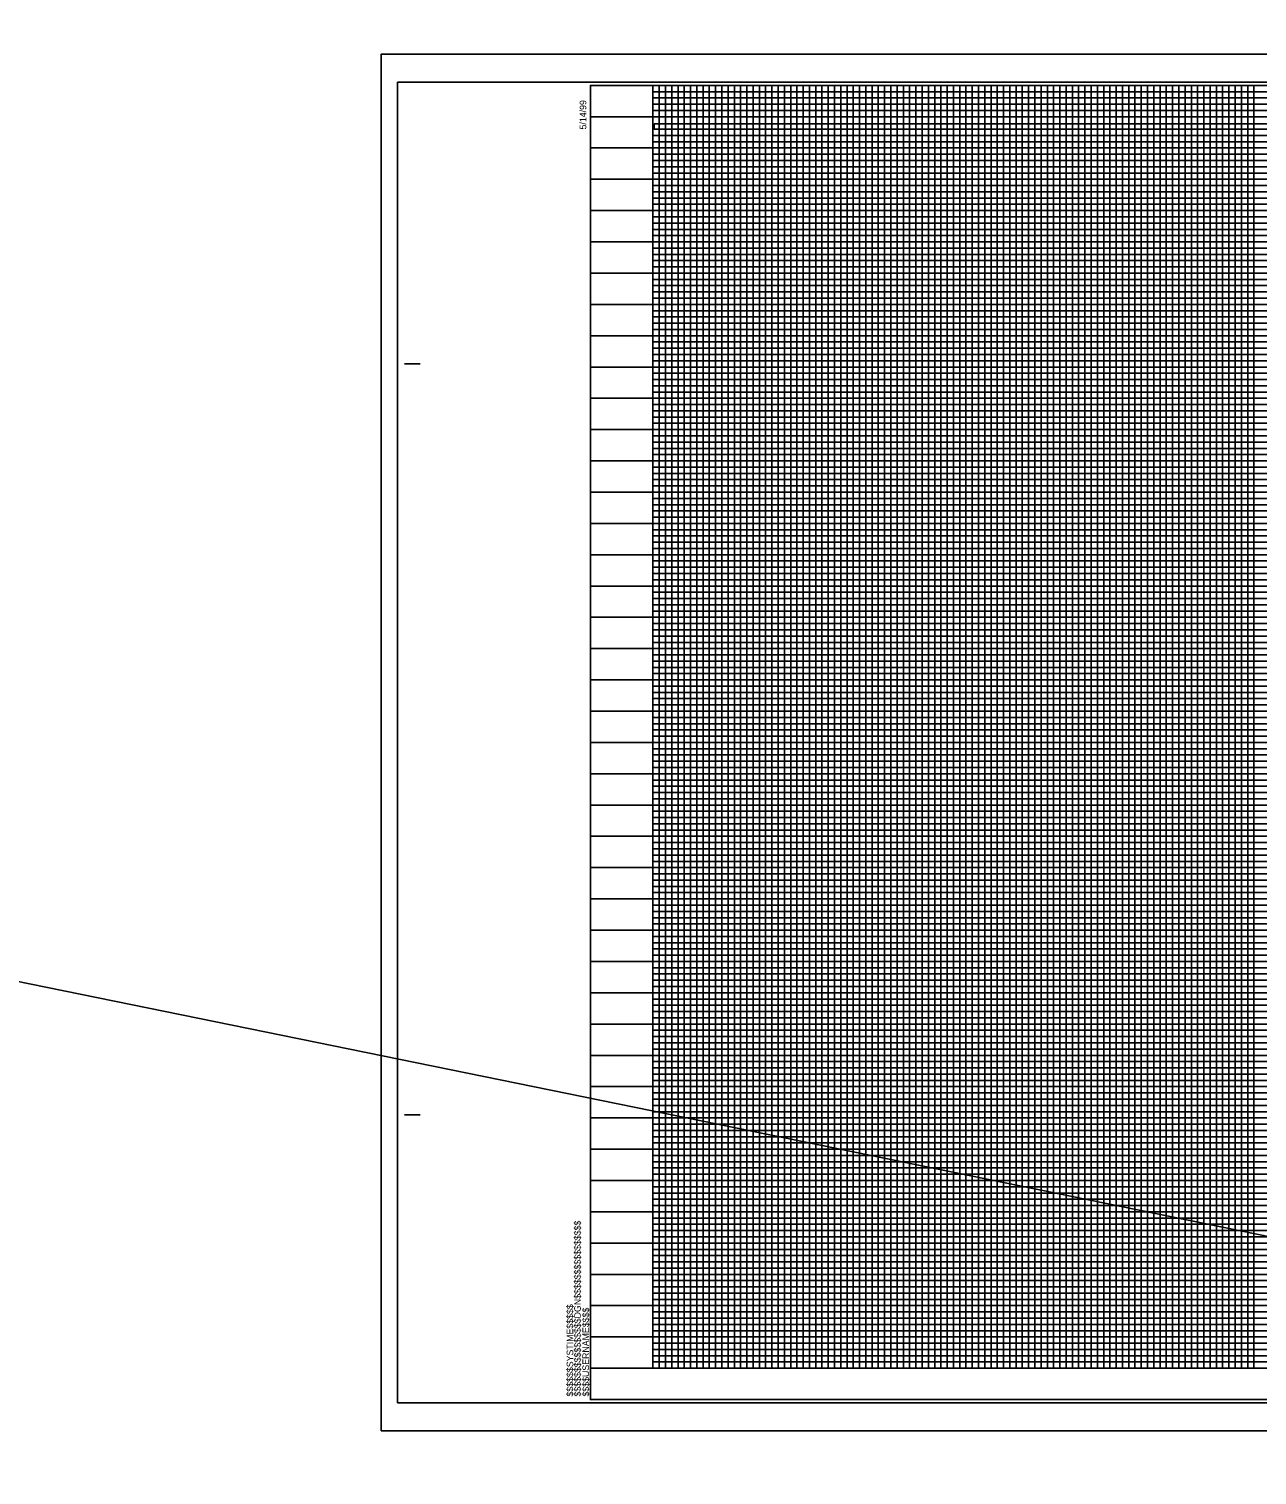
# Model space of a CAD drawing. Extents: x 2345490 to 2445302, y 465165 to 573888.
# Drawn here: x 2381268 to 2382249, y 553101 to 554257 of the extents above; entities that cross this region are included whole.
import ezdxf

# ---------------------------------------------------------------- set-up
doc = ezdxf.new("R2010")
doc.units = 0
for name, color, linetype in [('Old_Level_18', 7, 'Continuous'), ('Old_Level_40', 7, 'Continuous'), ('Old_Level_41', 7, 'Continuous'), ('Old_Level_42', 7, 'Continuous'), ('Old_Level_43', 7, 'Continuous'), ('Old_Level_50', 7, 'Continuous'), ('Old_Level_51', 7, 'Continuous'), ('Old_Level_52', 7, 'Continuous'), ('Old_Level_62', 7, 'Continuous')]:
    doc.layers.add(name, color=color, linetype=linetype)

msp = doc.modelspace()

# ---------------------------------------------------------------- linework, layer by layer
at = {"layer": 'Old_Level_18'}
msp.add_line((2381716.79875, 553161.782), (2381716.79875, 553161.782), dxfattribs=at)
msp.add_line((2381716.79875, 553161.782), (2381716.79875, 553161.782), dxfattribs=at)
msp.add_lwpolyline([(2383216.79875, 554211.782), (2381716.79875, 554211.782), (2381716.79875, 553161.782), (2383216.79875, 553161.782)], close=True, dxfattribs=at)
at = {"layer": 'Old_Level_40'}
msp.add_line((2381716.79875, 553161.782), (2381716.79875, 553161.782), dxfattribs=at)
msp.add_line((2381716.79875, 553161.782), (2381716.79875, 553161.782), dxfattribs=at)
msp.add_line((2381716.79875, 553161.782), (2381716.79875, 553161.782), dxfattribs=at)
msp.add_line((2381716.79875, 553161.782), (2381716.79875, 553161.782), dxfattribs=at)
at = {"layer": 'Old_Level_41'}
for p, q in [((2381568.29875, 553989.282), (2381580.79875, 553989.282)), ((2381568.29875, 553389.282), (2381580.79875, 553389.282)), ((2383216.79875, 553186.782), (2381716.79875, 553186.782))]:
    msp.add_line(p, q, dxfattribs=at)
for points in [[(2381716.79875, 554211.782), (2381766.79875, 554211.782), (2381766.79875, 553186.782), (2381816.79875, 553186.782), (2381816.79875, 554211.782), (2381866.79875, 554211.782), (2381866.79875, 553186.782), (2381916.79875, 553186.782), (2381916.79875, 554211.782), (2381966.79875, 554211.782), (2381966.79875, 553186.782), (2382016.79875, 553186.782), (2382016.79875, 554211.782), (2382066.79875, 554211.782), (2382066.79875, 553186.782), (2382116.79875, 553186.782), (2382116.79875, 554211.782), (2382166.79875, 554211.782), (2382166.79875, 553186.782), (2382216.79875, 553186.782), (2382216.79875, 554211.782), (2382266.79875, 554211.782)], [(2381791.79875, 553186.782), (2381791.79875, 554211.782), (2381841.79875, 554211.782), (2381841.79875, 553186.782), (2381891.79875, 553186.782), (2381891.79875, 554211.782), (2381941.79875, 554211.782), (2381941.79875, 553186.782), (2381991.79875, 553186.782), (2381991.79875, 554211.782), (2382041.79875, 554211.782), (2382041.79875, 553186.782), (2382091.79875, 553186.782), (2382091.79875, 554211.782), (2382141.79875, 554211.782), (2382141.79875, 553186.782), (2382191.79875, 553186.782), (2382191.79875, 554211.782), (2382241.79875, 554211.782), (2382241.79875, 553186.782), (2382291.79875, 553186.782)], [(2381716.79875, 554161.782), (2383016.74875, 554161.782)], [(2383016.74875, 554111.782), (2381716.79875, 554111.782), (2381716.79875, 554061.732), (2383216.79875, 554061.732)], [(2383216.79875, 554036.782), (2381716.79875, 554036.782), (2381716.79875, 554086.782), (2383016.74875, 554086.782)], [(2383216.79875, 554011.782), (2381716.79875, 554011.782), (2381716.79875, 553961.782), (2383216.79875, 553961.782)], [(2383216.79875, 553936.782), (2381716.79875, 553936.782), (2381716.79875, 553986.782), (2383216.79875, 553986.782)], [(2383216.79875, 553911.782), (2381716.79875, 553911.782), (2381716.79875, 553861.782), (2383216.79875, 553861.782)], [(2383216.79875, 553811.782), (2381716.79875, 553811.782), (2381716.79875, 553761.782), (2383216.79875, 553761.782)], [(2383216.79875, 553711.782), (2381716.79875, 553711.782), (2381716.79875, 553661.782), (2383216.79875, 553661.782)], [(2383216.79875, 553611.782), (2381716.79875, 553611.782), (2381716.79875, 553561.782), (2383216.79875, 553561.782)], [(2383216.79875, 553536.782), (2381716.79875, 553536.782), (2381716.79875, 553586.782), (2383216.79875, 553586.782)], [(2383216.79875, 553511.782), (2381716.79875, 553511.782), (2381716.79875, 553461.782), (2383216.79875, 553461.782)], [(2383216.79875, 553436.782), (2381716.79875, 553436.782), (2381716.79875, 553486.782), (2383216.79875, 553486.782)], [(2383216.79875, 553411.782), (2381716.79875, 553411.782), (2381716.79875, 553361.782), (2383216.79875, 553361.782)], [(2383216.79875, 553311.782), (2381716.79875, 553311.782), (2381716.79875, 553261.782), (2383216.79875, 553261.782)], [(2383216.79875, 553236.782), (2381716.79875, 553236.782), (2381716.79875, 553286.782), (2383216.79875, 553286.782)], [(2383216.79875, 553211.782), (2381716.79875, 553211.782)], [(2381754.29875, 553161.782), (2381754.29875, 553161.782)]]:
    msp.add_lwpolyline(points, dxfattribs=at)
at = {"layer": 'Old_Level_42'}
for points in [[(2383016.74875, 554136.782), (2381716.89875, 554136.782), (2381716.89875, 554186.732), (2383016.74875, 554186.732)], [(2383216.79875, 553836.782), (2381716.79875, 553836.782), (2381716.79875, 553886.782), (2383216.79875, 553886.782)], [(2383216.79875, 553736.782), (2381716.79875, 553736.782), (2381716.79875, 553786.782), (2383216.79875, 553786.782)], [(2383216.79875, 553636.782), (2381716.79875, 553636.782), (2381716.79875, 553686.782), (2383216.79875, 553686.782)], [(2383216.79875, 553336.782), (2381716.79875, 553336.782), (2381716.79875, 553386.782), (2383216.79875, 553386.782)]]:
    msp.add_lwpolyline(points, dxfattribs=at)
at = {"layer": 'Old_Level_43'}
for p, q in [((2383166.79875, 554031.782), (2381766.79875, 554031.782)), ((2381766.79875, 554031.782), (2381766.79875, 554026.782)), ((2381766.79875, 554026.782), (2383166.79875, 554026.782)), ((2383166.79875, 554006.782), (2381766.79875, 554006.782))]:
    msp.add_line(p, q, dxfattribs=at)
for points in [[(2381771.79875, 554211.782), (2381776.79875, 554211.782), (2381781.79875, 554211.782), (2381786.79875, 554211.782), (2381796.79875, 554211.782), (2381763.74875, 554211.782), (2381768.74875, 554211.782), (2381726.79875, 554211.782), (2381731.79875, 554211.782), (2381736.79875, 554211.782), (2381746.79875, 554211.782), (2381751.79875, 554211.782), (2381756.79875, 554211.782), (2381761.79875, 554211.782), (2381771.79875, 554211.782), (2381771.79875, 553186.782), (2381776.79875, 553186.782), (2381776.79875, 554211.782), (2381781.79875, 554211.782), (2381781.79875, 553186.782), (2381786.79875, 553186.782), (2381786.79875, 554211.782), (2381796.79875, 554211.782), (2381796.79875, 553186.782), (2381801.79875, 553186.782), (2381801.79875, 554211.782), (2381806.79875, 554211.782), (2381806.79875, 553186.782), (2381811.79875, 553186.782), (2381811.79875, 554211.782), (2381821.79875, 554211.782), (2381821.79875, 553186.782), (2381826.79875, 553186.782), (2381826.79875, 554211.782), (2381831.79875, 554211.782), (2381831.79875, 553186.782), (2381836.79875, 553186.782), (2381836.79875, 554211.782), (2381846.79875, 554211.782), (2381846.79875, 553186.782), (2381851.79875, 553186.782), (2381851.79875, 554211.782), (2381856.79875, 554211.782), (2381856.79875, 553186.782), (2381861.79875, 553186.782), (2381861.79875, 554211.782), (2381871.79875, 554211.782), (2381871.79875, 553186.782), (2381876.79875, 553186.782), (2381876.79875, 554211.782), (2381881.79875, 554211.782), (2381881.79875, 553186.782), (2381886.79875, 553186.782), (2381886.79875, 554211.782), (2381896.79875, 554211.782), (2381896.79875, 553186.782), (2381901.79875, 553186.782), (2381901.79875, 554211.782), (2381906.79875, 554211.782), (2381906.79875, 553186.782), (2381911.79875, 553186.782), (2381911.79875, 554211.782), (2381921.79875, 554211.782), (2381921.79875, 553186.782), (2381926.79875, 553186.782), (2381926.79875, 554211.782), (2381931.79875, 554211.782), (2381931.79875, 553186.782)], [(2383016.74875, 554206.782), (2381766.79875, 554206.782), (2381766.79875, 554201.782), (2383016.74875, 554201.782)], [(2381931.79875, 553186.782), (2381936.79875, 553186.782), (2381936.79875, 554211.782), (2381946.79875, 554211.782), (2381946.79875, 553186.782), (2381951.79875, 553186.782), (2381951.79875, 554211.782), (2381956.79875, 554211.782), (2381956.79875, 553186.782), (2381961.79875, 553186.782), (2381961.79875, 554211.782), (2381971.79875, 554211.782), (2381971.79875, 553186.782), (2381976.79875, 553186.782), (2381976.79875, 554211.782), (2381976.79875, 554211.782), (2381981.79875, 554211.782), (2381981.79875, 553186.782), (2381986.79875, 553186.782), (2381986.79875, 554211.782), (2381996.79875, 554211.782), (2381996.79875, 553186.782), (2382001.79875, 553186.782), (2382001.79875, 554211.782), (2382006.79875, 554211.782), (2382006.79875, 553186.782), (2382011.79875, 553186.782), (2382011.79875, 554211.782), (2382021.79875, 554211.782), (2382021.79875, 553186.782), (2382026.79875, 553186.782), (2382026.79875, 554211.782), (2382031.79875, 554211.782), (2382031.79875, 553186.782), (2382036.79875, 553186.782), (2382036.79875, 554211.782), (2382046.79875, 554211.782), (2382046.79875, 553186.782), (2382051.79875, 553186.782), (2382051.79875, 554211.782), (2382056.79875, 554211.782), (2382056.79875, 553186.782), (2382061.79875, 553186.782), (2382061.79875, 554211.782), (2382071.79875, 554211.782), (2382071.79875, 553186.782), (2382076.79875, 553186.782), (2382076.79875, 554211.782), (2382081.79875, 554211.782), (2382081.79875, 553186.782), (2382086.79875, 553186.782), (2382086.79875, 554211.782), (2382096.79875, 554211.782), (2382096.79875, 553186.782), (2382111.79875, 553186.782), (2382111.79875, 554211.782), (2382121.79875, 554211.782), (2382121.79875, 553186.782), (2382126.79875, 553186.782), (2382126.79875, 554211.782), (2382131.79875, 554211.782), (2382131.79875, 553186.782), (2382136.79875, 553186.782), (2382136.79875, 554211.782), (2382146.79875, 554211.782), (2382146.79875, 553186.782), (2382151.79875, 553186.782), (2382151.79875, 554211.782), (2382156.79875, 554211.782), (2382156.79875, 553186.782), (2382161.79875, 553186.782), (2382161.79875, 554211.782), (2382171.79875, 554211.782), (2382171.79875, 553186.782), (2382176.79875, 553186.782), (2382176.79875, 554211.782), (2382181.79875, 554211.782), (2382181.79875, 553186.782), (2382186.79875, 553186.782), (2382186.79875, 554211.782), (2382196.79875, 554211.782), (2382196.79875, 553186.782), (2382201.79875, 553186.782), (2382201.79875, 554211.782), (2382206.79875, 554211.782), (2382206.79875, 553186.782), (2382211.79875, 553186.782), (2382211.79875, 554211.782), (2382221.79875, 554211.782), (2382221.79875, 553186.782), (2382226.79875, 553186.782), (2382226.79875, 554211.782), (2382231.79875, 554211.782), (2382231.79875, 553186.782), (2382236.79875, 553186.782), (2382236.79875, 554211.782), (2382246.79875, 554211.782), (2382246.79875, 553186.782)], [(2382101.79875, 554211.782), (2382101.79875, 553186.782), (2382106.79875, 553186.782), (2382106.79875, 554211.782)], [(2382101.79875, 554211.182), (2382101.79875, 553186.782), (2382106.79875, 553186.782), (2382106.79875, 554211.182)], [(2383016.74875, 554196.782), (2381766.79875, 554196.782), (2381766.79875, 554191.782), (2383016.74875, 554191.782)], [(2383016.74875, 554181.032), (2381767.79875, 554181.032), (2381767.79875, 554176.782), (2383016.74875, 554176.782)], [(2383016.74875, 554171.782), (2381766.79875, 554171.782), (2381766.79875, 554166.782), (2383016.74875, 554166.782)], [(2383016.74875, 554156.782), (2381766.79875, 554156.782), (2381766.79875, 554151.782), (2383016.74875, 554151.782)], [(2383016.74875, 554146.782), (2381766.79875, 554146.782), (2381766.79875, 554141.782), (2383016.74875, 554141.782)], [(2383016.74875, 554131.782), (2381766.79875, 554131.782), (2381766.79875, 554126.782), (2383016.74875, 554126.782)], [(2383016.74875, 554121.782), (2381766.79875, 554121.782), (2381766.79875, 554116.782), (2383016.74875, 554116.782)], [(2383016.74875, 554106.782), (2381766.79875, 554106.782), (2381766.79875, 554101.782), (2383016.74875, 554101.782)], [(2383016.74875, 554096.782), (2381766.79875, 554096.782), (2381766.79875, 554091.782), (2383016.74875, 554091.782)], [(2383016.74875, 554081.782), (2381766.79875, 554081.782), (2381766.79875, 554076.782), (2383016.74875, 554076.782)], [(2383166.79875, 554071.782), (2381766.79875, 554071.782), (2381766.79875, 554071.782), (2381766.79875, 554051.782), (2383166.79875, 554051.782)], [(2381766.79875, 554066.782), (2383166.79875, 554066.782)], [(2383166.79875, 554056.782), (2381766.79875, 554056.782)], [(2383166.79875, 554046.782), (2381766.79875, 554046.782), (2381766.79875, 554041.782), (2383166.79875, 554041.782)], [(2383166.79875, 554021.782), (2381766.79875, 554021.782), (2381766.79875, 554016.782), (2383166.79875, 554016.782)], [(2383166.79875, 554001.782), (2381766.79875, 554001.782), (2381766.79875, 553996.782), (2383166.79875, 553996.782)], [(2383166.79875, 553991.782), (2381766.79875, 553991.782)], [(2381766.79875, 553981.782), (2383166.79875, 553981.782)], [(2383166.79875, 553976.782), (2381766.79875, 553976.782), (2381766.79875, 553971.782), (2383166.79875, 553971.782)], [(2383166.79875, 553966.782), (2381766.79875, 553966.782), (2381766.79875, 553956.782), (2383166.79875, 553956.782)], [(2383166.79875, 553951.782), (2381766.79875, 553951.782), (2381766.79875, 553946.782), (2383166.79875, 553946.782)], [(2383166.79875, 553941.782), (2381766.79875, 553941.782), (2381766.79875, 553931.782), (2383166.79875, 553931.782)], [(2383166.79875, 553926.782), (2381766.79875, 553926.782), (2381766.79875, 553921.782), (2383166.79875, 553921.782)], [(2383166.79875, 553916.782), (2381766.79875, 553916.782), (2381766.79875, 553906.782), (2383166.79875, 553906.782)], [(2383166.79875, 553901.782), (2381766.79875, 553901.782), (2381766.79875, 553896.782), (2383166.79875, 553896.782)], [(2383166.79875, 553891.782), (2381766.79875, 553891.782), (2381766.79875, 553881.782), (2383166.79875, 553881.782)], [(2383166.79875, 553876.782), (2381766.79875, 553876.782), (2381766.79875, 553871.782), (2383166.79875, 553871.782)], [(2383166.79875, 553866.782), (2381766.79875, 553866.782), (2381766.79875, 553856.782), (2383166.79875, 553856.782)], [(2383166.79875, 553851.782), (2381766.79875, 553851.782), (2381766.79875, 553846.782), (2383166.79875, 553846.782)], [(2383166.79875, 553841.782), (2381766.79875, 553841.782), (2381766.79875, 553831.782), (2383166.79875, 553831.782)], [(2383166.79875, 553826.782), (2381766.79875, 553826.782), (2381766.79875, 553821.782), (2383166.79875, 553821.782)], [(2383166.79875, 553816.782), (2381766.79875, 553816.782), (2381766.79875, 553806.782), (2383166.79875, 553806.782)], [(2383166.79875, 553801.782), (2381766.79875, 553801.782), (2381766.79875, 553796.782), (2383166.79875, 553796.782)], [(2383166.79875, 553791.782), (2381766.79875, 553791.782), (2381766.79875, 553781.782), (2383166.79875, 553781.782)], [(2383166.79875, 553776.782), (2381766.79875, 553776.782), (2381766.79875, 553771.782), (2383166.79875, 553771.782)], [(2383166.79875, 553766.782), (2381766.79875, 553766.782), (2381766.79875, 553756.782), (2383166.79875, 553756.782)], [(2383166.79875, 553751.782), (2381766.79875, 553751.782), (2381766.79875, 553746.782), (2383166.79875, 553746.782)], [(2383166.79875, 553741.782), (2381766.79875, 553741.782), (2381766.79875, 553731.782), (2383166.79875, 553731.782)], [(2383166.79875, 553726.782), (2381766.79875, 553726.782), (2381766.79875, 553721.782), (2383166.79875, 553721.782)], [(2383166.79875, 553716.782), (2381766.79875, 553716.782), (2381766.79875, 553706.782), (2383166.79875, 553706.782)], [(2383166.79875, 553701.782), (2381766.79875, 553701.782), (2381766.79875, 553696.782), (2383166.79875, 553696.782)], [(2383166.79875, 553691.782), (2381766.79875, 553691.782)], [(2381766.79875, 553681.782), (2383166.79875, 553681.782)], [(2383166.79875, 553676.782), (2381766.79875, 553676.782), (2381766.79875, 553671.782), (2383166.79875, 553671.782)], [(2383166.79875, 553666.782), (2381766.79875, 553666.782), (2381766.79875, 553656.782), (2383166.79875, 553656.782)], [(2383166.79875, 553651.782), (2381766.79875, 553651.782), (2381766.79875, 553646.782), (2383166.79875, 553646.782)], [(2383166.79875, 553641.782), (2381766.79875, 553641.782), (2381766.79875, 553631.782), (2383166.79875, 553631.782)], [(2383166.79875, 553626.782), (2381766.79875, 553626.782), (2381766.79875, 553621.782), (2383166.79875, 553621.782)], [(2383166.79875, 553616.782), (2381766.79875, 553616.782), (2381766.79875, 553606.782), (2383166.79875, 553606.782)], [(2383166.79875, 553601.782), (2381766.79875, 553601.782), (2381766.79875, 553596.782), (2383166.79875, 553596.782)], [(2383166.79875, 553591.782), (2381766.79875, 553591.782), (2381766.79875, 553581.782), (2383166.79875, 553581.782)], [(2383166.79875, 553576.782), (2381766.79875, 553576.782), (2381766.79875, 553571.782), (2383166.79875, 553571.782)], [(2383166.79875, 553566.782), (2381766.79875, 553566.782), (2381766.79875, 553556.782), (2383166.79875, 553556.782)], [(2383166.79875, 553551.782), (2381766.79875, 553551.782), (2381766.79875, 553546.782), (2383166.79875, 553546.782)], [(2383166.79875, 553541.782), (2381766.79875, 553541.782), (2381766.79875, 553531.782), (2383166.79875, 553531.782)], [(2383166.79875, 553526.782), (2381766.79875, 553526.782), (2381766.79875, 553521.782), (2383166.79875, 553521.782)], [(2383166.79875, 553516.782), (2381766.79875, 553516.782), (2381766.79875, 553506.782), (2383166.79875, 553506.782)], [(2383166.79875, 553501.782), (2381766.79875, 553501.782), (2381766.79875, 553496.782), (2383166.79875, 553496.782)], [(2383166.79875, 553491.782), (2381766.79875, 553491.782), (2381766.79875, 553481.782), (2383166.79875, 553481.782)], [(2383166.79875, 553476.782), (2381766.79875, 553476.782), (2381766.79875, 553471.782), (2383166.79875, 553471.782)], [(2383166.79875, 553466.782), (2381766.79875, 553466.782), (2381766.79875, 553456.782), (2383166.79875, 553456.782)], [(2383166.79875, 553451.782), (2381766.79875, 553451.782), (2381766.79875, 553446.782), (2383166.79875, 553446.782)], [(2383166.79875, 553441.782), (2381766.79875, 553441.782), (2381766.79875, 553431.782), (2383166.79875, 553431.782)], [(2383166.79875, 553426.782), (2381766.79875, 553426.782), (2381766.79875, 553421.782), (2383166.79875, 553421.782)], [(2383166.79875, 553416.782), (2381766.79875, 553416.782), (2381766.79875, 553406.782), (2383166.79875, 553406.782)], [(2383166.79875, 553401.782), (2381766.79875, 553401.782), (2381766.79875, 553396.782), (2383166.79875, 553396.782)], [(2383166.79875, 553391.782), (2381766.79875, 553391.782)], [(2381766.79875, 553381.782), (2383166.79875, 553381.782)], [(2383166.79875, 553376.782), (2381766.79875, 553376.782), (2381766.79875, 553371.782), (2383166.79875, 553371.782)], [(2383166.79875, 553366.782), (2381766.79875, 553366.782)], [(2381766.79875, 553356.782), (2383166.79875, 553356.782)], [(2383166.79875, 553351.782), (2381766.79875, 553351.782), (2381766.79875, 553346.782), (2383166.79875, 553346.782)], [(2383166.79875, 553341.782), (2381766.79875, 553341.782), (2381766.79875, 553331.782), (2383166.79875, 553331.782)], [(2383166.79875, 553326.782), (2381766.79875, 553326.782), (2381766.79875, 553321.782), (2383166.79875, 553321.782)], [(2383166.79875, 553316.782), (2381766.79875, 553316.782), (2381766.79875, 553306.782), (2383166.79875, 553306.782)], [(2383166.79875, 553301.782), (2381766.79875, 553301.782), (2381766.79875, 553296.782), (2383166.79875, 553296.782)], [(2383166.79875, 553291.782), (2381766.79875, 553291.782), (2381766.79875, 553281.782), (2383166.79875, 553281.782)], [(2383166.79875, 553276.782), (2381766.79875, 553276.782), (2381766.79875, 553271.782), (2383166.79875, 553271.782)], [(2383166.79875, 553266.782), (2381766.79875, 553266.782), (2381766.79875, 553256.782), (2383166.79875, 553256.782)], [(2383166.79875, 553251.782), (2381766.79875, 553251.782), (2381766.79875, 553246.782), (2383166.79875, 553246.782)], [(2383166.79875, 553241.782), (2381766.79875, 553241.782), (2381766.79875, 553231.782), (2383166.79875, 553231.782)], [(2383166.79875, 553226.782), (2381766.79875, 553226.782), (2381766.79875, 553221.782), (2383166.79875, 553221.782)], [(2383166.79875, 553216.782), (2381766.79875, 553216.782), (2381766.79875, 553206.782), (2383166.79875, 553206.782)], [(2383166.79875, 553201.782), (2381766.79875, 553201.782), (2381766.79875, 553196.782), (2383166.79875, 553196.782)], [(2383166.79875, 553191.782), (2381766.79875, 553191.782)]]:
    msp.add_lwpolyline(points, dxfattribs=at)
at = {"layer": 'Old_Level_50'}
msp.add_line((2381549.79875, 553136.782), (2381549.79875, 553136.782), dxfattribs=at)
msp.add_lwpolyline([(2383229.29875, 554214.332), (2381562.79875, 554214.332), (2381562.79875, 553159.232), (2383229.29875, 553159.232)], close=True, dxfattribs=at)
at = {"layer": 'Old_Level_51'}
msp.add_lwpolyline([(2383233.79875, 554236.782), (2381549.79875, 554236.782), (2381549.79875, 553136.782), (2383233.79875, 553136.782)], close=True, dxfattribs=at)
at = {"layer": 'Old_Level_52'}
msp.add_line((2381562.79875, 553159.232), (2381562.79875, 553159.232), dxfattribs=at)
at = {"layer": 'Old_Level_62'}
msp.add_line((2409193.67257, 547800.0936), (2373316.48805, 555115.25837), dxfattribs=at)

# ---------------------------------------------------------------- texts
at = {"layer": 'Old_Level_41'}
for s, p in [('5/14/99', (2381713.54875, 554176.582)), ('$$$$$$$$$$$$$$$$DGN$$$$$$$$$$$$$$$$', (2381709.14875, 553164.1445)), ('$$$$$$SYSTIME$$$$$', (2381703.09875, 553164.1445)), ('$$$$USERNAME$$$$', (2381715.72375, 553164.157))]:
    msp.add_text(s, height=5.25, rotation=90, dxfattribs=at).set_placement(p)

doc.saveas('drawing.dxf')
